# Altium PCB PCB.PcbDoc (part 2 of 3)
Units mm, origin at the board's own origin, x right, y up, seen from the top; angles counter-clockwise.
Board outline 120 x 100 mm, 4 copper layers (Top Layer, Mid-Layer 1, Mid-Layer 2, Bottom Layer); 85 components, 69 nets, 423 pads, 4470 vias.
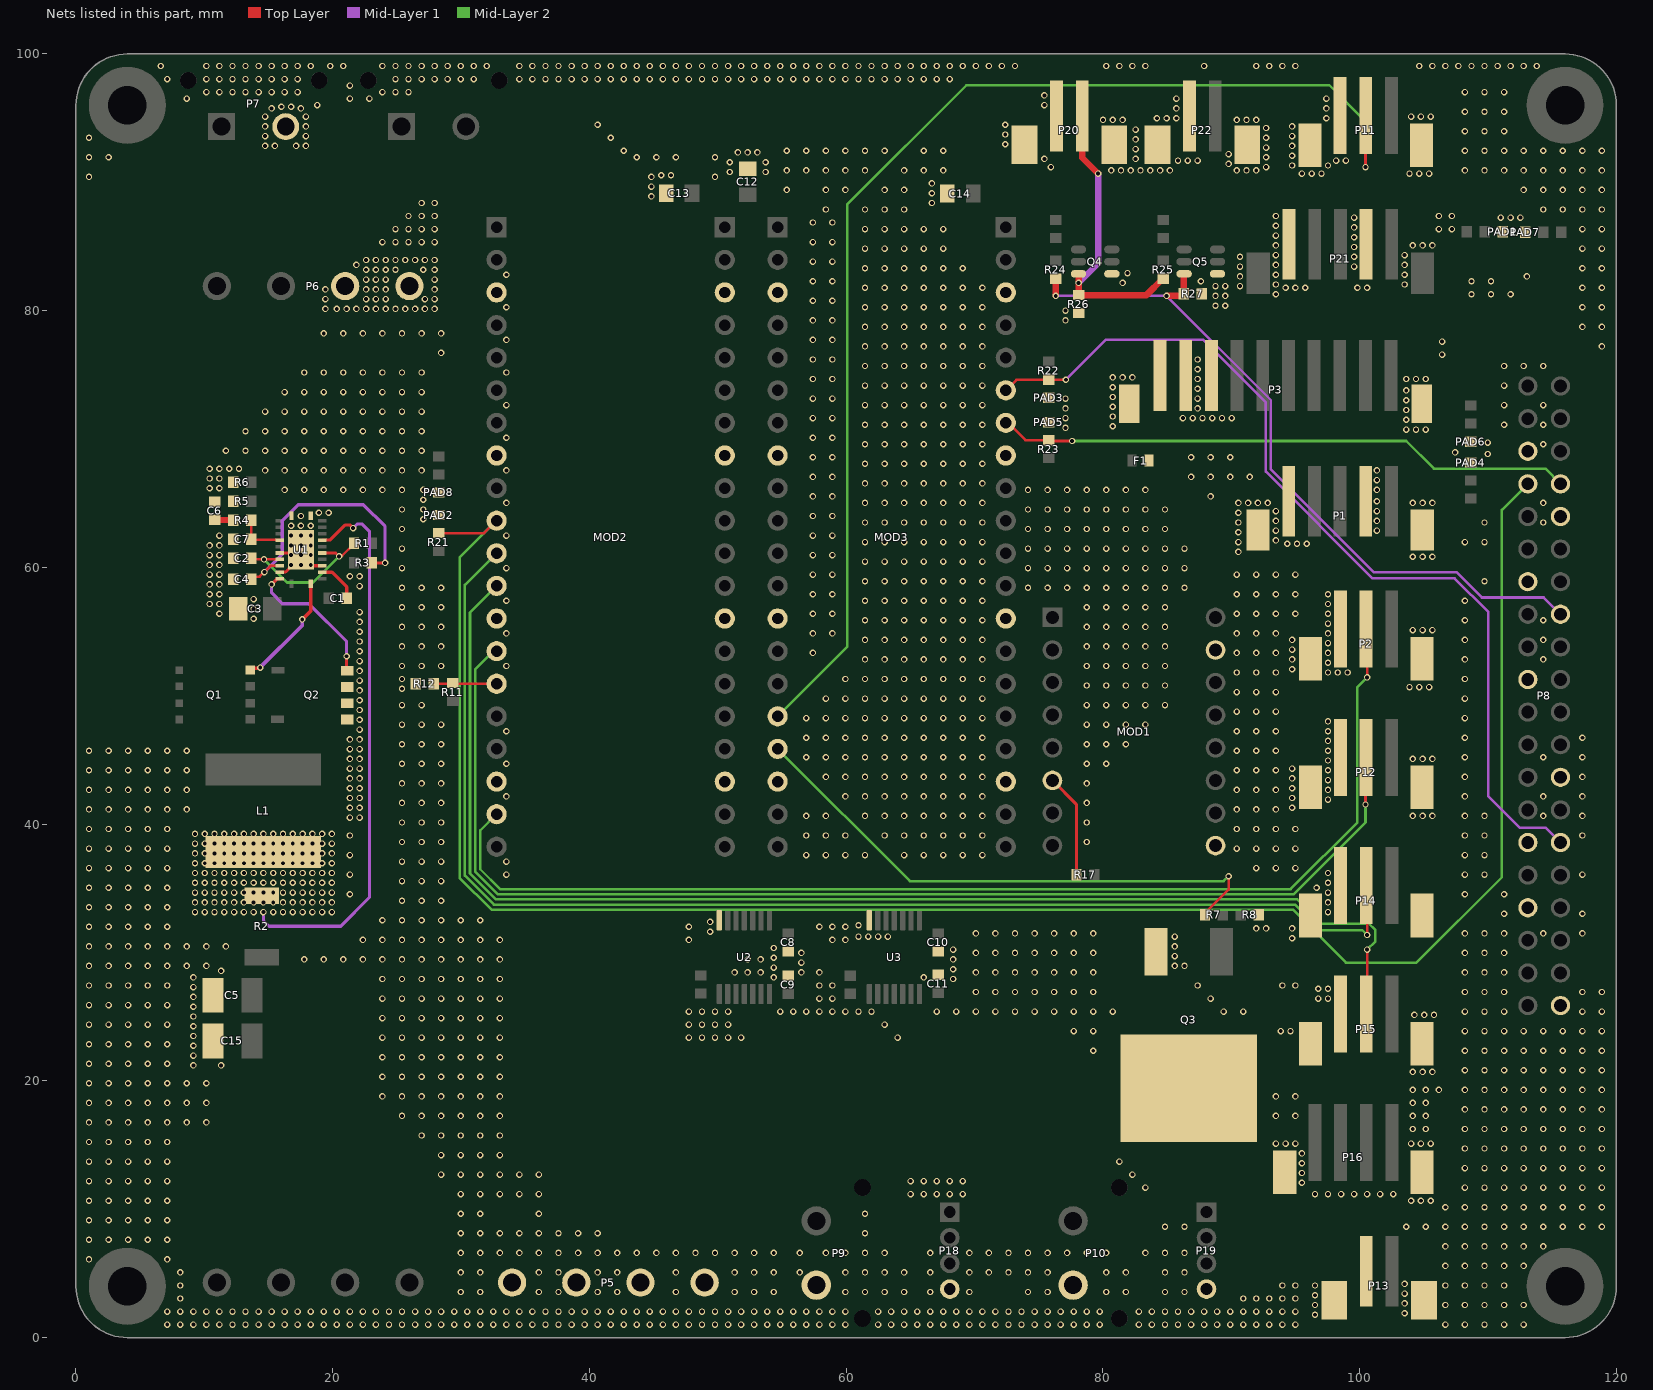
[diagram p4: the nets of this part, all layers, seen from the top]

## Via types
v1: diameter 0.5, hole 0.3, Top Layer to Bottom Layer, 4470 vias

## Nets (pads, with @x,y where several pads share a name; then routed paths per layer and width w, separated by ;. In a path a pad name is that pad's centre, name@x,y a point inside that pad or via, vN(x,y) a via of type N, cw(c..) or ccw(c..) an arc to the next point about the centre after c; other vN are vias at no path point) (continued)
ESP32-1_GPIO_18: MOD2.10 P8.8 R21.1 | length 152.1
  Top Layer w0.2: R21.1@28.245,62.676 31.802,62.676 MOD2.10@32.766,63.64
  Mid-Layer 2 w0.2: MOD2.10@32.766,63.64 29.896,60.77 29.896,35.824 32.385,33.335 94.808,33.335 98.933,29.21 104.419,29.21 111.074,35.865 111.074,64.478 P8.8@113.106,66.51
ESP32-1_GPIO_33: MOD2.11 P14.2 | length 102.2
  Top Layer w0.2: P14.2@100.514,35.206 100.584,35.136 v1(100.584,31.369)
  Mid-Layer 2 w0.2: MOD2.11@32.766,61.1 30.296,58.63 30.296,35.99 32.551,33.735 94.974,33.735 96.959,31.75 100.203,31.75 v1(100.584,31.369)
ESP32-1_GPIO_34: MOD2.12 P15.2 | length 102.4
  Top Layer w0.2: P15.2@100.514,25.206 100.584,25.275 v1(100.584,30.226)
  Mid-Layer 2 w0.2: MOD2.12@32.766,58.56 30.696,56.49 30.696,36.156 32.717,34.135 95.139,34.135 97.016,32.258 100.711,32.258 101.219,31.75 101.219,30.861 v1(100.584,30.226)
ESP32-1_GPIO_35: MOD2.14 P12.2 | length 95.5
  Top Layer w0.2: v1(100.457,41.529) 100.457,45.155 P12.2@100.508,45.206
  Mid-Layer 2 w0.2: MOD2.14@32.766,53.48 32.525,53.48 31.096,52.051 31.096,36.321 32.882,34.535 94.86,34.535 100.457,40.132 v1(100.457,41.529)
ESP32-1_GPIO_36: MOD2.15 R11.1 R12.2 | length 4.9
  Top Layer w0.2: R12.2@27.878,51.054 27.992,50.94 MOD2.15@32.766,50.94
ESP32-1_GPIO_39: MOD2.19 P2.2 | length 91.4
  Top Layer w0.2: P2.2@100.508,55.206 100.584,55.13 v1(100.584,51.435)
  Mid-Layer 2 w0.2: MOD2.19@32.766,40.78 31.496,39.51 31.496,36.487 33.048,34.935 94.625,34.935 99.822,40.132 99.822,50.673 v1(100.584,51.435)
ESP32-2_GPIO_9: MOD3.34 P8.7 R23.1 | length 45.2
  Top Layer w0.2: MOD3.34@72.44,71.26 72.631,71.26 73.973,69.918 R23.1@75.795,69.918 75.854,69.977 75.981,69.85 v1(77.597,69.85)
  Mid-Layer 2 w0.2: v1(77.597,69.85) 103.632,69.85 105.791,67.691 114.465,67.691 P8.7@115.646,66.51
ESP32-2_GPIO_10: MOD3.35 P8.29 R22.1 | length 72.6
  Top Layer w0.2: MOD3.35@72.44,73.8 73.254,74.614 R22.1@75.796,74.614 75.807,74.625 v1(77.114,74.625)
  Mid-Layer 1 w0.2: v1(77.114,74.625) 80.239,77.749 87.801,77.749 92.691,72.859 92.691,67.456 100.995,59.152 107.396,59.152 110.033,56.515 110.033,42.164 112.471,39.726 114.491,39.726 P8.29@115.646,38.57
ESP32-2_GPIO_37: MOD3.16 P11.2 | length 95.1
  Top Layer w0.2: v1(100.457,91.186) 100.457,95.187 P11.2@100.476,95.206
  Mid-Layer 2 w0.2: MOD3.16@54.66,48.4 60.071,53.811 60.071,88.265 69.367,97.561 97.638,97.561 100.457,94.742 v1(100.457,91.186)
ESP32-2_GPIO_38: MOD3.17 R7.2 | length 43.4
  Top Layer w0.2: R7.2@87.946,32.944 87.884,33.006 89.789,34.911 v1(89.789,35.941)
  Mid-Layer 2 w0.2: MOD3.17@54.66,45.86 64.96,35.56 89.408,35.56 v1(89.789,35.941)
FLP/FLP_INPUT1: P20.1 Q4.3 R25.2 R26.2 | length 22.9
  Top Layer w0.5: Q4.3@78.1,82.87 78.103,82.868 78.103,81.22 R26.2@78.105,81.218 83.392,81.218 84.659,82.485 R25.2@84.709,82.485 ; P20.1@78.389,95.168 78.389,91.918 v1(79.629,90.678)
  Mid-Layer 1 w0.5: v1(78.105,82.169) 79.629,83.693 v1(79.629,90.678)
FLP/FLP_INPUT2_RSPI22: P8.15 Q5.3 R24.1 R27.2 | length 57.2
  Top Layer w0.5: v1(76.327,81.153) 76.327,82.231 76.454,82.358 R24.1@76.327,82.485 ; v1(84.963,81.153) 86.143,81.153 R27.2@86.295,81.306 86.313,81.323 86.313,82.853 Q5.3@86.33,82.87
  Mid-Layer 1 w0.2: v1(76.327,81.153) v1(84.963,81.153) 93.091,73.025 93.091,67.64 101.092,59.639 107.544,59.639 109.525,57.658 114.338,57.658 P8.15@115.646,56.35
GND: C2.2 C3.1 C4.1 C5.1 C6.2 C7.2 C8.1 C9.1 C10.1 C11.1 C12.1 C13.1 C14.1 C15.1 MOD1.9 MOD1.15 MOD2.3 MOD2.8 MOD2.13 MOD2.18 MOD2.23 MOD2.28 MOD2.33 MOD2.38 MOD3.3 MOD3.8 MOD3.13 MOD3.18 MOD3.23 MOD3.28 MOD3.33 MOD3.38 P1.2 P1.5 P1.MP P2.3 P2.MP P3.8 P3.9 P3.MP P5.1 P5.2 P5.3 P5.4 P6.3 P6.4 P7.2 P8.6 P8.9 P8.14 P8.20 P8.25 P8.30 P8.34 P8.39 P9.2 P10.2 P11.3 P11.MP P12.3 P12.MP P13.MP P14.3 P14.MP P15.3 P15.MP P16.MP P18.4 P19.4 P20.2 P20.MP P21.2 P21.5 P22.2 P22.MP PAD1.1 PAD2.1 PAD3.1 PAD4.1 PAD5.1 PAD6.1 PAD7.1 PAD8.1 Q2.1 Q2.2 Q2.3 Q3.3 Q4.4 Q5.4 R5.2 R6.2 R8.1 R12.1 R26.1 R27.1 U1.1 U1.7 U1.10 U1.16 U1.24 U1.25 U2.7 U3.7 | length 3.1
  Top Layer w0.25: U1.10@15.88,59.626 15.895,59.641 16.328,59.641 16.764,60.077 v1(16.764,60.198) ; U1.7@15.88,61.126 16.598,61.126 v1(16.764,60.96) ; v1(18.288,60.198) 18.36,60.126 U1.16@19.195,60.126
  other v1: 7.112,1.016 8.128,1.016 9.144,1.016 10.16,1.016 11.176,1.016 12.192,1.016 13.208,1.016 14.224,1.016 15.24,1.016 16.256,1.016 17.272,1.016 18.288,1.016 19.304,1.016 20.32,1.016 21.336,1.016 22.352,1.016 23.368,1.016 24.384,1.016 25.4,1.016 26.416,1.016 27.432,1.016 28.448,1.016 29.464,1.016 30.48,1.016 31.496,1.016 32.512,1.016 33.528,1.016 34.544,1.016 35.56,1.016 36.576,1.016 37.592,1.016 38.608,1.016 39.624,1.016 40.64,1.016 41.656,1.016 42.672,1.016 43.688,1.016 44.704,1.016 45.72,1.016 46.736,1.016 47.752,1.016 48.768,1.016 49.784,1.016 50.8,1.016 51.816,1.016 52.832,1.016 53.848,1.016 54.864,1.016 55.88,1.016 56.896,1.016 57.912,1.016 58.928,1.016 59.944,1.016 62.484,1.016 63.5,1.016 64.516,1.016 65.532,1.016 66.548,1.016 67.564,1.016 68.58,1.016 69.596,1.016 70.612,1.016 71.628,1.016 72.644,1.016 73.66,1.016 74.676,1.016 75.692,1.016 76.708,1.016 77.724,1.016 78.74,1.016 79.756,1.016 82.804,1.016 83.82,1.016 84.836,1.016 85.852,1.016 86.868,1.016 87.884,1.016 88.9,1.016 89.916,1.016 90.932,1.016 91.948,1.016 92.964,1.016 93.98,1.016 94.996,1.016 106.68,1.016 108.204,1.016 109.728,1.016 111.252,1.016 112.776,1.016 96.52,1.778 103.505,1.905 7.112,2.032 8.128,2.032 9.144,2.032 10.16,2.032 11.176,2.032 12.192,2.032 13.208,2.032 14.224,2.032 15.24,2.032 16.256,2.032 17.272,2.032 18.288,2.032 19.304,2.032 20.32,2.032 21.336,2.032 22.352,2.032 23.368,2.032 24.384,2.032 25.4,2.032 26.416,2.032 27.432,2.032 28.448,2.032 29.464,2.032 30.48,2.032 31.496,2.032 32.512,2.032 33.528,2.032 34.544,2.032 35.56,2.032 36.576,2.032 37.592,2.032 38.608,2.032 39.624,2.032 40.64,2.032 41.656,2.032 42.672,2.032 43.688,2.032 44.704,2.032 45.72,2.032 46.736,2.032 47.752,2.032 48.768,2.032 49.784,2.032 50.8,2.032 51.816,2.032 52.832,2.032 53.848,2.032 54.864,2.032 55.88,2.032 56.896,2.032 57.912,2.032 58.928,2.032 59.944,2.032 62.484,2.032 63.5,2.032 64.516,2.032 65.532,2.032 66.548,2.032 67.564,2.032 68.58,2.032 69.596,2.032 70.612,2.032 71.628,2.032 72.644,2.032 73.66,2.032 74.676,2.032 75.692,2.032 76.708,2.032 77.724,2.032 78.74,2.032 79.756,2.032 82.804,2.032 83.82,2.032 84.836,2.032 85.852,2.032 86.868,2.032 87.884,2.032 88.9,2.032 89.916,2.032 90.932,2.032 91.948,2.032 92.964,2.032 93.98,2.032 94.996,2.032 96.52,2.54 106.68,2.54 108.204,2.54 109.728,2.54 111.252,2.54 112.776,2.54 103.505,2.667 8.128,3.048 90.932,3.048 91.948,3.048 92.964,3.048 93.98,3.048 94.996,3.048 96.52,3.302 103.505,3.429 29.972,3.556 31.496,3.556 36.068,3.556 37.592,3.556 40.64,3.556 42.164,3.556 46.736,3.556 51.308,3.556 52.832,3.556 54.356,3.556 59.944,3.556 61.468,3.556 62.992,3.556 64.516,3.556 66.548,3.556 69.596,3.556 74.168,3.556 75.692,3.556 80.264,3.556 81.788,3.556 84.836,3.556 86.36,3.556 8.128,4.064 93.98,4.064 94.996,4.064 96.52,4.064 106.68,4.064 108.204,4.064 109.728,4.064 111.252,4.064 103.505,4.191 8.128,5.08 29.972,5.08 31.496,5.08 36.068,5.08 37.592,5.08 40.64,5.08 42.164,5.08 46.736,5.08 51.308,5.08 52.832,5.08 54.356,5.08 56.388,5.08 59.944,5.08 61.468,5.08 62.992,5.08 64.516,5.08 66.548,5.08 69.596,5.08 71.12,5.08 72.644,5.08 74.168,5.08 75.692,5.08 80.264,5.08 81.788,5.08 84.836,5.08 86.36,5.08 106.68,5.588 108.204,5.588 109.728,5.588 111.252,5.588 112.776,5.588 1.016,6.096 7.112,6.096 29.972,6.604 31.496,6.604 33.02,6.604 34.544,6.604 36.068,6.604 37.592,6.604 39.116,6.604 40.64,6.604 42.164,6.604 43.688,6.604 45.212,6.604 46.736,6.604 48.26,6.604 49.784,6.604 51.308,6.604 52.832,6.604 54.356,6.604 56.388,6.604 58.42,6.604 59.944,6.604 61.468,6.604 62.992,6.604 66.548,6.604 69.596,6.604 71.12,6.604 72.644,6.604 74.168,6.604 75.692,6.604 77.216,6.604 78.74,6.604 80.264,6.604 83.312,6.604 84.836,6.604 86.36,6.604 106.68,7.112 108.204,7.112 109.728,7.112 111.252,7.112 112.776,7.112 114.3,7.112 1.016,7.62 2.54,7.62 4.064,7.62 5.588,7.62 7.112,7.62 29.972,8.128 31.496,8.128 33.02,8.128 34.544,8.128 36.068,8.128 37.592,8.128 39.116,8.128 40.64,8.128 61.468,8.128 84.836,8.636 86.36,8.636 103.632,8.636 105.156,8.636 106.68,8.636 108.204,8.636 109.728,8.636 111.252,8.636 112.776,8.636 114.3,8.636 115.824,8.636 117.348,8.636 118.872,8.636 1.016,9.144 2.54,9.144 4.064,9.144 5.588,9.144 7.112,9.144 29.972,9.652 31.496,9.652 36.068,9.652 61.468,9.652 106.68,10.16 108.204,10.16 109.728,10.16 111.252,10.16 112.776,10.16 114.3,10.16 115.824,10.16 117.348,10.16 118.872,10.16 1.016,10.668 2.54,10.668 4.064,10.668 5.588,10.668 7.112,10.668 104.013,10.668 104.775,10.668 105.537,10.668 29.972,11.176 31.496,11.176 33.02,11.176 34.544,11.176 36.068,11.176 65.024,11.176 66.04,11.176 67.056,11.176 68.072,11.176 69.088,11.176 96.52,11.176 97.536,11.176 98.552,11.176 99.568,11.176 100.584,11.176 101.6,11.176 102.616,11.176 83.312,11.684 108.204,11.684 109.728,11.684 111.252,11.684 112.776,11.684 114.3,11.684 115.824,11.684 117.348,11.684 118.872,11.684 95.504,12.065 1.016,12.192 2.54,12.192 4.064,12.192 5.588,12.192 7.112,12.192 65.024,12.192 66.04,12.192 67.056,12.192 68.072,12.192 69.088,12.192 28.448,12.7 29.972,12.7 31.496,12.7 33.02,12.7 34.544,12.7 36.068,12.7 82.296,12.7 95.504,12.827 108.204,13.208 109.728,13.208 111.252,13.208 112.776,13.208 114.3,13.208 115.824,13.208 117.348,13.208 118.872,13.208 95.504,13.589 1.016,13.716 2.54,13.716 4.064,13.716 5.588,13.716 7.112,13.716 81.28,13.716 28.448,14.224 29.972,14.224 31.496,14.224 33.02,14.224 95.504,14.351 108.204,14.732 109.728,14.732 111.252,14.732 112.776,14.732 114.3,14.732 115.824,14.732 117.348,14.732 118.872,14.732 93.472,15.113 94.234,15.113 94.996,15.113 104.013,15.113 104.775,15.113 105.537,15.113 1.016,15.24 2.54,15.24 4.064,15.24 5.588,15.24 7.112,15.24 26.924,15.748 28.448,15.748 29.972,15.748 31.496,15.748 33.02,15.748 104.14,16.256 105.156,16.256 108.204,16.256 109.728,16.256 111.252,16.256 112.776,16.256 114.3,16.256 115.824,16.256 117.348,16.256 118.872,16.256 1.016,16.764 2.54,16.764 4.064,16.764 5.588,16.764 7.112,16.764 8.636,16.764 10.16,16.764 25.4,17.272 26.924,17.272 28.448,17.272 29.972,17.272 31.496,17.272 33.02,17.272 93.472,17.272 94.996,17.272 104.14,17.272 105.156,17.272 108.204,17.78 109.728,17.78 111.252,17.78 112.776,17.78 114.3,17.78 115.824,17.78 117.348,17.78 118.872,17.78 1.016,18.288 2.54,18.288 4.064,18.288 5.588,18.288 7.112,18.288 8.636,18.288 10.16,18.288 104.14,18.288 105.156,18.288 23.876,18.796 25.4,18.796 26.924,18.796 28.448,18.796 29.972,18.796 31.496,18.796 33.02,18.796 93.472,18.796 94.996,18.796 104.14,19.304 105.156,19.304 106.172,19.304 108.204,19.304 109.728,19.304 111.252,19.304 112.776,19.304 114.3,19.304 115.824,19.304 117.348,19.304 118.872,19.304 1.016,19.812 2.54,19.812 4.064,19.812 5.588,19.812 7.112,19.812 8.636,19.812 10.16,19.812 23.876,20.32 25.4,20.32 26.924,20.32 28.448,20.32 29.972,20.32 31.496,20.32 33.02,20.32 104.14,20.701 104.902,20.701 105.664,20.701 108.204,20.828 109.728,20.828 111.252,20.828 112.776,20.828 114.3,20.828 115.824,20.828 117.348,20.828 118.872,20.828 9.144,21.209 11.303,21.209 1.016,21.336 2.54,21.336 4.064,21.336 5.588,21.336 7.112,21.336 23.876,21.844 25.4,21.844 26.924,21.844 28.448,21.844 29.972,21.844 31.496,21.844 33.02,21.844 9.144,21.971 79.248,22.352 108.204,22.352 109.728,22.352 111.252,22.352 112.776,22.352 114.3,22.352 115.824,22.352 117.348,22.352 118.872,22.352 9.144,22.733 1.016,22.86 2.54,22.86 4.064,22.86 5.588,22.86 7.112,22.86 23.876,23.368 25.4,23.368 26.924,23.368 28.448,23.368 29.972,23.368 31.496,23.368 33.02,23.368 47.752,23.368 48.768,23.368 49.784,23.368 50.8,23.368 51.816,23.368 64.008,23.368 9.144,23.495 77.724,23.876 79.248,23.876 93.853,23.876 94.615,23.876 108.204,23.876 109.728,23.876 111.252,23.876 112.776,23.876 114.3,23.876 115.824,23.876 117.348,23.876 118.872,23.876 9.144,24.257 1.016,24.384 2.54,24.384 4.064,24.384 5.588,24.384 7.112,24.384 47.752,24.384 48.768,24.384 49.784,24.384 50.8,24.384 62.992,24.384 23.876,24.892 25.4,24.892 26.924,24.892 28.448,24.892 29.972,24.892 31.496,24.892 33.02,24.892 9.144,25.019 104.267,25.146 105.029,25.146 105.791,25.146 47.752,25.4 48.768,25.4 49.784,25.4 50.8,25.4 54.864,25.4 55.88,25.4 56.896,25.4 57.912,25.4 58.928,25.4 59.944,25.4 60.96,25.4 61.976,25.4 67.056,25.4 68.58,25.4 70.104,25.4 71.628,25.4 73.152,25.4 74.676,25.4 76.2,25.4 77.724,25.4 79.248,25.4 80.772,25.4 89.408,25.4 90.932,25.4 108.204,25.4 109.728,25.4 111.252,25.4 117.348,25.4 118.872,25.4 9.144,25.781 1.016,25.908 2.54,25.908 4.064,25.908 5.588,25.908 7.112,25.908 23.876,26.416 25.4,26.416 26.924,26.416 28.448,26.416 29.972,26.416 31.496,26.416 33.02,26.416 57.912,26.416 58.928,26.416 88.392,26.416 96.774,26.416 97.536,26.416 9.144,26.543 70.104,26.924 71.628,26.924 73.152,26.924 74.676,26.924 76.2,26.924 77.724,26.924 79.248,26.924 108.204,26.924 109.728,26.924 111.252,26.924 117.348,26.924 118.872,26.924 96.774,27.178 97.536,27.178 9.144,27.305 1.016,27.432 2.54,27.432 4.064,27.432 5.588,27.432 7.112,27.432 57.912,27.432 58.928,27.432 87.376,27.432 93.98,27.432 94.996,27.432 23.876,27.94 25.4,27.94 26.924,27.94 28.448,27.94 29.972,27.94 31.496,27.94 33.02,27.94 68.326,27.94 9.144,28.067 54.356,28.067 66.04,28.067 51.308,28.448 52.324,28.448 53.34,28.448 56.515,28.448 57.912,28.448 70.104,28.448 71.628,28.448 73.152,28.448 74.676,28.448 76.2,28.448 77.724,28.448 79.248,28.448 108.204,28.448 109.728,28.448 111.252,28.448 11.303,28.575 68.326,28.702 54.356,28.829 1.016,28.956 2.54,28.956 4.064,28.956 5.588,28.956 7.112,28.956 8.636,28.956 10.16,28.956 85.598,28.956 86.36,28.956 56.515,29.21 17.78,29.464 19.304,29.464 20.828,29.464 22.352,29.464 23.876,29.464 25.4,29.464 26.924,29.464 28.448,29.464 29.972,29.464 31.496,29.464 33.02,29.464 52.324,29.464 53.34,29.464 68.326,29.464 54.356,29.591 85.598,29.718 56.515,29.972 70.104,29.972 71.628,29.972 73.152,29.972 74.676,29.972 76.2,29.972 77.724,29.972 79.248,29.972 108.204,29.972 109.728,29.972 111.252,29.972 68.326,30.226 54.356,30.353 1.016,30.48 2.54,30.48 4.064,30.48 5.588,30.48 7.112,30.48 8.636,30.48 10.16,30.48 11.684,30.48 85.598,30.48 22.352,30.988 23.876,30.988 25.4,30.988 26.924,30.988 28.448,30.988 29.972,30.988 31.496,30.988 33.02,30.988 47.752,30.988 58.928,30.988 59.944,30.988 94.742,31.115 60.96,31.242 61.722,31.242 62.484,31.242 63.246,31.242 85.598,31.242 70.104,31.496 71.628,31.496 73.152,31.496 74.676,31.496 76.2,31.496 77.724,31.496 79.248,31.496 108.204,31.496 109.728,31.496 111.252,31.496 114.3,31.496 117.348,31.496 49.403,31.623 91.948,31.877 92.71,31.877 94.742,31.877 1.016,32.004 2.54,32.004 4.064,32.004 5.588,32.004 7.112,32.004 47.752,32.004 57.912,32.004 58.928,32.004 59.944,32.004 60.96,32.131 49.403,32.385 23.876,32.512 25.4,32.512 26.924,32.512 28.448,32.512 29.972,32.512 31.496,32.512 111.252,33.02 117.348,33.02 97.536,33.147 1.016,33.528 2.54,33.528 4.064,33.528 5.588,33.528 7.112,33.528 97.536,33.909 25.4,34.036 26.924,34.036 28.448,34.036 21.336,34.544 108.204,34.544 111.252,34.544 97.536,34.671 1.016,35.052 2.54,35.052 4.064,35.052 5.588,35.052 7.112,35.052 96.647,35.052 97.536,35.433 25.4,35.56 26.924,35.56 28.448,35.56 21.336,36.068 33.528,36.068 108.204,36.068 109.728,36.068 117.348,36.068 97.536,36.195 1.016,36.576 2.54,36.576 4.064,36.576 5.588,36.576 7.112,36.576 91.948,36.576 93.472,36.576 94.996,36.576 25.4,37.084 26.924,37.084 28.448,37.084 33.528,37.084 21.336,37.592 56.896,37.592 58.42,37.592 59.944,37.592 61.468,37.592 64.516,37.592 66.04,37.592 67.564,37.592 69.088,37.592 70.612,37.592 108.204,37.592 109.728,37.592 1.016,38.1 2.54,38.1 4.064,38.1 5.588,38.1 7.112,38.1 90.424,38.1 91.948,38.1 93.472,38.1 94.996,38.1 25.4,38.608 26.924,38.608 28.448,38.608 78.74,38.608 21.336,39.116 56.896,39.116 58.42,39.116 59.944,39.116 62.992,39.116 64.516,39.116 66.04,39.116 67.564,39.116 69.088,39.116 70.612,39.116 108.204,39.116 109.728,39.116 117.348,39.116 1.016,39.624 2.54,39.624 4.064,39.624 5.588,39.624 7.112,39.624 90.424,39.624 91.948,39.624 93.472,39.624 94.996,39.624 25.4,40.132 26.924,40.132 28.448,40.132 78.74,40.132 21.336,40.513 22.098,40.513 56.896,40.64 58.42,40.64 61.468,40.64 62.992,40.64 64.516,40.64 66.04,40.64 67.564,40.64 69.088,40.64 70.612,40.64 104.14,40.64 104.902,40.64 105.664,40.64 108.204,40.64 109.728,40.64 114.3,40.64 117.348,40.64 1.016,41.148 2.54,41.148 4.064,41.148 5.588,41.148 7.112,41.148 8.636,41.148 90.424,41.148 91.948,41.148 93.472,41.148 21.336,41.275 22.098,41.275 94.742,41.275 25.4,41.656 26.924,41.656 28.448,41.656 78.74,41.656 97.536,41.91 21.336,42.037 22.098,42.037 94.742,42.037 33.528,42.164 59.944,42.164 61.468,42.164 62.992,42.164 64.516,42.164 66.04,42.164 67.564,42.164 69.088,42.164 70.612,42.164 108.204,42.164 114.3,42.164 117.348,42.164 1.016,42.672 2.54,42.672 4.064,42.672 5.588,42.672 7.112,42.672 8.636,42.672 90.424,42.672 91.948,42.672 93.472,42.672 97.536,42.672 21.336,42.799 22.098,42.799 94.742,42.799 25.4,43.18 26.924,43.18 28.448,43.18 78.74,43.18 97.536,43.434 21.336,43.561 22.098,43.561 94.742,43.561 58.42,43.688 59.944,43.688 61.468,43.688 62.992,43.688 64.516,43.688 66.04,43.688 67.564,43.688 69.088,43.688 70.612,43.688 108.204,43.688 117.348,43.688 1.016,44.196 2.54,44.196 4.064,44.196 5.588,44.196 7.112,44.196 8.636,44.196 90.424,44.196 91.948,44.196 93.472,44.196 97.536,44.196 21.336,44.323 22.098,44.323 94.742,44.323 25.4,44.704 26.924,44.704 28.448,44.704 33.528,44.704 78.74,44.704 80.264,44.704 97.536,44.958 21.336,45.085 22.098,45.085 104.14,45.085 104.902,45.085 105.664,45.085 56.896,45.212 58.42,45.212 59.944,45.212 61.468,45.212 62.992,45.212 64.516,45.212 66.04,45.212 67.564,45.212 69.088,45.212 70.612,45.212 108.204,45.212 114.3,45.212 117.348,45.212 1.016,45.72 2.54,45.72 4.064,45.72 5.588,45.72 7.112,45.72 8.636,45.72 90.424,45.72 91.948,45.72 93.472,45.72 97.536,45.72 21.336,45.847 22.098,45.847 25.4,46.228 26.924,46.228 28.448,46.228 78.74,46.228 80.264,46.228 81.788,46.228 97.536,46.482 21.336,46.609 22.098,46.609 56.896,46.736 58.42,46.736 59.944,46.736 61.468,46.736 62.992,46.736 64.516,46.736 66.04,46.736 67.564,46.736 69.088,46.736 70.612,46.736 108.204,46.736 117.348,46.736 33.528,47.244 90.424,47.244 91.948,47.244 93.472,47.244 97.536,47.244 22.098,47.371 25.4,47.752 26.924,47.752 28.448,47.752 78.74,47.752 80.264,47.752 81.788,47.752 83.312,47.752 97.536,48.006 22.098,48.133 56.896,48.26 58.42,48.26 59.944,48.26 61.468,48.26 62.992,48.26 64.516,48.26 66.04,48.26 67.564,48.26 69.088,48.26 70.612,48.26 108.204,48.26 90.424,48.768 91.948,48.768 93.472,48.768 22.098,48.895 25.4,49.276 26.924,49.276 78.74,49.276 80.264,49.276 81.788,49.276 83.312,49.276 84.836,49.276 22.098,49.657 58.42,49.784 59.944,49.784 61.468,49.784 62.992,49.784 64.516,49.784 66.04,49.784 67.564,49.784 69.088,49.784 70.612,49.784 108.204,49.784 90.424,50.292 91.948,50.292 93.472,50.292 22.098,50.419 25.4,50.546 103.886,50.673 104.648,50.673 105.41,50.673 78.74,50.8 80.264,50.8 81.788,50.8 83.312,50.8 84.836,50.8 22.098,51.181 25.4,51.308 59.944,51.308 61.468,51.308 62.992,51.308 64.516,51.308 66.04,51.308 67.564,51.308 69.088,51.308 70.612,51.308 108.204,51.308 90.424,51.816 91.948,51.816 93.472,51.816 97.536,51.816 98.298,51.816 99.06,51.816 22.098,51.943 94.742,52.07 25.4,52.324 26.924,52.324 28.448,52.324 33.528,52.324 78.74,52.324 80.264,52.324 81.788,52.324 83.312,52.324 84.836,52.324 97.536,52.578 22.098,52.705 61.468,52.832 62.992,52.832 64.516,52.832 66.04,52.832 67.564,52.832 69.088,52.832 70.612,52.832 94.742,52.832 108.204,52.832 114.3,52.832 57.404,53.34 90.424,53.34 91.948,53.34 93.472,53.34 97.536,53.34 22.098,53.467 94.742,53.594 25.4,53.848 26.924,53.848 28.448,53.848 78.74,53.848 80.264,53.848 81.788,53.848 83.312,53.848 84.836,53.848 97.536,54.102 22.098,54.229 61.468,54.356 62.992,54.356 64.516,54.356 66.04,54.356 67.564,54.356 69.088,54.356 70.612,54.356 94.742,54.356 108.204,54.356 114.3,54.356 33.528,54.864 57.404,54.864 58.928,54.864 90.424,54.864 91.948,54.864 93.472,54.864 97.536,54.864 22.098,54.991 104.14,55.118 104.902,55.118 105.664,55.118 25.4,55.372 26.924,55.372 28.448,55.372 78.74,55.372 80.264,55.372 81.788,55.372 83.312,55.372 84.836,55.372 97.536,55.626 22.098,55.753 61.468,55.88 62.992,55.88 64.516,55.88 66.04,55.88 67.564,55.88 69.088,55.88 70.612,55.88 108.204,55.88 114.3,55.88 13.843,56.007 11.176,56.388 57.404,56.388 58.928,56.388 90.424,56.388 91.948,56.388 93.472,56.388 94.996,56.388 97.536,56.388 22.098,56.515 13.843,56.769 25.4,56.896 26.924,56.896 28.448,56.896 78.74,56.896 80.264,56.896 81.788,56.896 83.312,56.896 84.836,56.896 10.414,57.15 11.176,57.15 97.536,57.15 33.528,57.404 61.468,57.404 62.992,57.404 64.516,57.404 66.04,57.404 67.564,57.404 69.088,57.404 70.612,57.404 108.204,57.404 13.843,57.531 10.414,57.912 11.176,57.912 57.404,57.912 58.928,57.912 90.424,57.912 91.948,57.912 93.472,57.912 94.996,57.912 97.536,57.912 25.4,58.42 26.924,58.42 28.448,58.42 74.168,58.42 75.692,58.42 77.216,58.42 78.74,58.42 80.264,58.42 81.788,58.42 83.312,58.42 84.836,58.42 86.36,58.42 22.098,58.547 10.414,58.674 11.176,58.674 61.468,58.928 62.992,58.928 64.516,58.928 66.04,58.928 67.564,58.928 69.088,58.928 70.612,58.928 109.728,58.928 21.336,59.309 22.098,59.309 10.414,59.436 11.176,59.436 57.404,59.436 58.928,59.436 90.424,59.436 91.948,59.436 93.472,59.436 94.996,59.436 25.4,59.944 33.528,59.944 74.168,59.944 75.692,59.944 77.216,59.944 78.74,59.944 80.264,59.944 81.788,59.944 83.312,59.944 84.836,59.944 86.36,59.944 10.414,60.198 11.176,60.198 17.526,60.198 61.468,60.452 62.992,60.452 64.516,60.452 66.04,60.452 67.564,60.452 69.088,60.452 70.612,60.452 104.14,60.833 104.902,60.833 105.664,60.833 10.414,60.96 11.176,60.96 17.526,60.96 18.288,60.96 57.404,60.96 58.928,60.96 90.551,61.214 25.4,61.468 74.168,61.468 75.692,61.468 77.216,61.468 78.74,61.468 80.264,61.468 81.788,61.468 83.312,61.468 84.836,61.468 86.36,61.468 10.414,61.722 11.176,61.722 16.764,61.722 17.526,61.722 18.288,61.722 94.361,61.849 95.123,61.849 95.885,61.849 61.468,61.976 62.992,61.976 64.516,61.976 66.04,61.976 67.564,61.976 69.088,61.976 70.612,61.976 90.551,61.976 108.204,61.976 109.728,61.976 93.472,62.103 11.176,62.484 16.764,62.484 17.526,62.484 18.288,62.484 33.528,62.484 57.404,62.484 58.928,62.484 90.551,62.738 93.472,62.865 101.346,62.865 25.4,62.992 74.168,62.992 75.692,62.992 77.216,62.992 78.74,62.992 80.264,62.992 81.788,62.992 83.312,62.992 84.836,62.992 16.764,63.246 17.526,63.246 18.288,63.246 61.468,63.5 62.992,63.5 64.516,63.5 66.04,63.5 67.564,63.5 69.088,63.5 70.612,63.5 90.551,63.5 109.728,63.5 114.3,63.5 93.472,63.627 101.346,63.627 27.051,63.754 17.526,64.008 57.404,64.008 58.928,64.008 18.923,64.262 19.685,64.262 90.551,64.262 93.472,64.389 101.346,64.389 25.4,64.516 27.051,64.516 74.168,64.516 75.692,64.516 77.216,64.516 78.74,64.516 80.264,64.516 81.788,64.516 83.312,64.516 84.836,64.516 33.528,65.024 61.468,65.024 62.992,65.024 64.516,65.024 66.04,65.024 67.564,65.024 69.088,65.024 70.612,65.024 90.551,65.024 91.313,65.024 92.075,65.024 92.837,65.024 104.14,65.024 104.902,65.024 105.664,65.024 114.3,65.024 101.346,65.151 27.051,65.278 57.404,65.532 58.928,65.532 88.392,65.532 16.256,66.04 17.78,66.04 19.304,66.04 20.828,66.04 22.352,66.04 23.876,66.04 25.4,66.04 27.051,66.04 74.168,66.04 75.692,66.04 77.216,66.04 78.74,66.04 80.264,66.04 81.788,66.04 83.312,66.04 101.346,66.04 10.414,66.167 11.176,66.167 61.468,66.548 62.992,66.548 64.516,66.548 66.04,66.548 67.564,66.548 69.088,66.548 70.612,66.548 101.346,66.802 10.414,66.929 11.176,66.929 57.404,67.056 58.928,67.056 86.868,67.056 88.392,67.056 89.916,67.056 91.44,67.056 14.732,67.564 16.256,67.564 17.78,67.564 19.304,67.564 20.828,67.564 22.352,67.564 23.876,67.564 25.4,67.564 26.924,67.564 33.528,67.564 101.346,67.564 10.414,67.691 11.176,67.691 11.938,67.691 12.7,67.691 61.468,68.072 62.992,68.072 64.516,68.072 66.04,68.072 67.564,68.072 69.088,68.072 70.612,68.072 57.404,68.58 58.928,68.58 86.868,68.58 88.392,68.58 89.916,68.58 109.982,68.834 107.442,68.961 11.684,69.088 13.208,69.088 14.732,69.088 16.256,69.088 17.78,69.088 19.304,69.088 20.828,69.088 22.352,69.088 23.876,69.088 25.4,69.088 26.924,69.088 61.468,69.596 62.992,69.596 64.516,69.596 66.04,69.596 67.564,69.596 69.088,69.596 70.612,69.596 114.3,69.596 109.982,69.723 33.528,70.104 57.404,70.104 58.928,70.104 13.208,70.612 14.732,70.612 16.256,70.612 17.78,70.612 19.304,70.612 20.828,70.612 22.352,70.612 23.876,70.612 25.4,70.612 26.924,70.612 103.632,70.739 104.394,70.739 105.156,70.739 77.089,70.866 80.772,70.993 61.468,71.12 62.992,71.12 64.516,71.12 66.04,71.12 67.564,71.12 69.088,71.12 70.612,71.12 111.252,71.12 114.3,71.12 103.632,71.501 57.404,71.628 58.928,71.628 77.089,71.628 86.233,71.628 86.995,71.628 87.757,71.628 88.519,71.628 89.281,71.628 90.043,71.628 80.772,71.755 14.732,72.136 16.256,72.136 17.78,72.136 19.304,72.136 20.828,72.136 22.352,72.136 23.876,72.136 25.4,72.136 26.924,72.136 103.632,72.263 77.089,72.39 87.376,72.39 80.772,72.517 33.528,72.644 61.468,72.644 62.992,72.644 64.516,72.644 66.04,72.644 67.564,72.644 69.088,72.644 70.612,72.644 111.252,72.644 114.3,72.644 103.632,73.025 57.404,73.152 58.928,73.152 77.089,73.152 87.376,73.152 80.772,73.279 16.256,73.66 17.78,73.66 19.304,73.66 20.828,73.66 22.352,73.66 23.876,73.66 25.4,73.66 26.924,73.66 103.632,73.787 87.376,73.914 80.772,74.041 61.468,74.168 62.992,74.168 64.516,74.168 66.04,74.168 67.564,74.168 69.088,74.168 70.612,74.168 111.252,74.168 57.404,74.676 58.928,74.676 87.376,74.676 103.632,74.676 104.394,74.676 105.156,74.676 80.772,74.803 81.534,74.803 82.296,74.803 17.78,75.184 19.304,75.184 20.828,75.184 22.352,75.184 23.876,75.184 25.4,75.184 26.924,75.184 33.528,75.184 87.376,75.438 61.468,75.692 62.992,75.692 64.516,75.692 66.04,75.692 67.564,75.692 69.088,75.692 70.612,75.692 111.252,75.692 112.776,75.692 114.3,75.692 57.404,76.2 58.928,76.2 87.376,76.2 106.426,76.581 28.448,76.708 61.468,77.216 62.992,77.216 64.516,77.216 66.04,77.216 67.564,77.216 69.088,77.216 70.612,77.216 118.872,77.216 106.426,77.597 33.528,77.724 57.404,77.724 58.928,77.724 19.304,78.232 20.828,78.232 22.352,78.232 23.876,78.232 25.4,78.232 26.924,78.232 28.448,78.232 61.468,78.74 62.992,78.74 64.516,78.74 66.04,78.74 67.564,78.74 69.088,78.74 70.612,78.74 117.348,78.74 118.872,78.74 57.404,79.248 58.928,79.248 77.089,79.248 77.089,80.01 19.431,80.137 20.32,80.137 21.082,80.137 21.844,80.137 22.606,80.137 23.368,80.137 24.13,80.137 24.892,80.137 25.654,80.137 26.416,80.137 27.178,80.137 27.94,80.137 33.528,80.264 61.468,80.264 62.992,80.264 64.516,80.264 66.04,80.264 67.564,80.264 69.088,80.264 70.612,80.264 117.348,80.264 118.872,80.264 88.773,80.391 89.535,80.391 57.404,80.772 58.928,80.772 19.431,80.899 22.606,80.899 23.368,80.899 24.13,80.899 27.178,80.899 27.94,80.899 88.773,81.153 89.535,81.153 93.472,81.28 108.712,81.28 110.236,81.28 111.76,81.28 19.431,81.661 22.606,81.661 23.368,81.661 24.13,81.661 27.94,81.661 61.468,81.788 62.992,81.788 64.516,81.788 66.04,81.788 67.564,81.788 69.088,81.788 70.612,81.788 94.234,81.788 94.996,81.788 95.758,81.788 99.822,81.788 100.584,81.788 117.348,81.788 118.872,81.788 88.773,81.915 89.535,81.915 90.678,81.915 93.472,82.042 103.505,82.042 81.534,82.169 57.404,82.296 58.928,82.296 87.63,82.296 108.712,82.296 110.236,82.296 22.606,82.423 23.368,82.423 24.13,82.423 27.94,82.423 90.678,82.677 113.03,82.677 33.528,82.804 93.472,82.804 103.505,82.804 81.915,82.931 22.606,83.185 23.368,83.185 24.13,83.185 24.892,83.185 27.051,83.185 27.94,83.185 61.468,83.312 62.992,83.312 64.516,83.312 66.04,83.312 67.564,83.312 69.088,83.312 117.348,83.312 118.872,83.312 90.678,83.439 99.568,83.439 21.844,83.566 93.472,83.566 103.505,83.566 57.404,83.82 58.928,83.82 22.606,83.947 23.368,83.947 24.13,83.947 24.892,83.947 25.654,83.947 26.416,83.947 27.178,83.947 27.94,83.947 90.678,84.201 99.568,84.201 93.472,84.328 103.505,84.328 61.468,84.836 62.992,84.836 64.516,84.836 66.04,84.836 67.564,84.836 117.348,84.836 118.872,84.836 99.568,84.963 93.472,85.09 104.14,85.09 104.902,85.09 105.664,85.09 23.876,85.344 24.892,85.344 25.908,85.344 26.924,85.344 27.94,85.344 57.404,85.344 58.928,85.344 99.568,85.725 93.472,85.852 24.892,86.36 25.908,86.36 26.924,86.36 27.94,86.36 61.468,86.36 62.992,86.36 64.516,86.36 66.04,86.36 67.564,86.36 106.172,86.36 107.188,86.36 117.348,86.36 118.872,86.36 99.568,86.487 93.472,86.614 57.404,86.868 58.928,86.868 99.568,87.249 110.998,87.249 111.76,87.249 112.522,87.249 25.908,87.376 26.924,87.376 27.94,87.376 93.472,87.376 106.172,87.376 107.188,87.376 58.42,87.884 61.468,87.884 62.992,87.884 64.516,87.884 114.3,87.884 115.824,87.884 117.348,87.884 118.872,87.884 26.924,88.392 27.94,88.392 66.675,88.392 44.831,88.9 66.675,89.154 55.372,89.408 58.42,89.408 59.944,89.408 62.992,89.408 64.516,89.408 112.776,89.408 114.3,89.408 115.824,89.408 117.348,89.408 118.872,89.408 44.831,89.662 66.675,89.916 1.016,90.424 44.831,90.424 49.784,90.424 45.593,90.551 46.355,90.551 95.504,90.678 96.266,90.678 97.028,90.678 103.886,90.678 104.648,90.678 105.41,90.678 50.927,90.805 53.721,90.805 55.372,90.932 56.896,90.932 58.42,90.932 59.944,90.932 61.468,90.932 64.516,90.932 66.04,90.932 67.564,90.932 80.645,90.932 81.407,90.932 82.169,90.932 82.931,90.932 83.693,90.932 84.455,90.932 85.217,90.932 90.424,90.932 91.186,90.932 91.948,90.932 108.204,90.932 109.728,90.932 111.252,90.932 112.776,90.932 114.3,90.932 115.824,90.932 117.348,90.932 118.872,90.932 75.946,91.186 92.71,91.186 94.742,91.313 97.536,91.313 89.789,91.44 50.927,91.567 53.721,91.567 85.852,91.694 86.614,91.694 87.376,91.694 98.171,91.694 98.933,91.694 75.438,91.821 82.55,91.821 1.016,91.948 2.54,91.948 43.688,91.948 45.212,91.948 46.736,91.948 49.784,91.948 92.71,91.948 94.742,92.075 89.789,92.202 51.562,92.329 52.324,92.329 53.086,92.329 42.672,92.456 55.372,92.456 56.896,92.456 58.42,92.456 59.944,92.456 61.468,92.456 62.992,92.456 66.04,92.456 67.564,92.456 108.204,92.456 109.728,92.456 111.252,92.456 112.776,92.456 114.3,92.456 115.824,92.456 117.348,92.456 118.872,92.456 82.55,92.583 92.71,92.71 14.732,92.837 15.494,92.837 17.145,92.837 17.907,92.837 94.742,92.837 72.39,92.964 82.55,93.345 1.016,93.472 41.656,93.472 92.71,93.472 14.732,93.599 17.907,93.599 94.742,93.599 72.39,93.726 108.204,93.98 109.728,93.98 111.252,93.98 82.55,94.107 92.71,94.234 14.732,94.361 17.907,94.361 94.742,94.361 40.64,94.488 72.39,94.488 80.01,94.869 80.772,94.869 81.534,94.869 90.424,94.869 91.186,94.869 91.948,94.869 84.201,94.996 84.963,94.996 85.725,94.996 97.409,94.996 14.732,95.123 17.907,95.123 104.013,95.123 104.775,95.123 105.537,95.123 108.204,95.504 109.728,95.504 111.252,95.504 15.24,95.758 17.526,95.758 85.725,95.758 97.409,95.758 16.002,95.885 16.764,95.885 18.796,96.012 75.438,96.012 8.636,96.52 21.336,96.52 22.86,96.52 85.725,96.52 97.409,96.52 75.438,96.774 10.16,97.028 11.176,97.028 12.192,97.028 13.208,97.028 14.224,97.028 15.24,97.028 16.256,97.028 17.272,97.028 23.876,97.028 24.892,97.028 25.908,97.028 108.204,97.028 109.728,97.028 111.252,97.028 21.336,97.536 7.112,98.044 10.16,98.044 11.176,98.044 12.192,98.044 13.208,98.044 14.224,98.044 15.24,98.044 16.256,98.044 17.272,98.044 24.892,98.044 25.908,98.044 26.924,98.044 27.94,98.044 28.956,98.044 29.972,98.044 30.988,98.044 34.544,98.044 35.56,98.044 36.576,98.044 37.592,98.044 38.608,98.044 39.624,98.044 40.64,98.044 41.656,98.044 42.672,98.044 43.688,98.044 44.704,98.044 45.72,98.044 46.736,98.044 47.752,98.044 48.768,98.044 49.784,98.044 50.8,98.044 51.816,98.044 52.832,98.044 53.848,98.044 54.864,98.044 55.88,98.044 56.896,98.044 57.912,98.044 58.928,98.044 59.944,98.044 60.96,98.044 61.976,98.044 62.992,98.044 64.008,98.044 65.024,98.044 66.04,98.044 67.056,98.044 68.072,98.044 6.604,99.06 10.16,99.06 11.176,99.06 12.192,99.06 13.208,99.06 14.224,99.06 15.24,99.06 16.256,99.06 17.272,99.06 18.288,99.06 19.812,99.06 20.828,99.06 23.876,99.06 24.892,99.06 25.908,99.06 26.924,99.06 27.94,99.06 28.956,99.06 29.972,99.06 30.988,99.06 32.004,99.06 34.544,99.06 35.56,99.06 36.576,99.06 37.592,99.06 38.608,99.06 39.624,99.06 40.64,99.06 41.656,99.06 42.672,99.06 43.688,99.06 44.704,99.06 45.72,99.06 46.736,99.06 47.752,99.06 48.768,99.06 49.784,99.06 50.8,99.06 51.816,99.06 52.832,99.06 53.848,99.06 54.864,99.06 55.88,99.06 56.896,99.06 57.912,99.06 58.928,99.06 59.944,99.06 60.96,99.06 61.976,99.06 62.992,99.06 64.008,99.06 65.024,99.06 66.04,99.06 67.056,99.06 68.072,99.06 69.088,99.06 70.104,99.06 71.12,99.06 72.136,99.06 73.152,99.06 80.264,99.06 81.28,99.06 82.296,99.06 83.312,99.06 87.884,99.06 91.948,99.06 92.964,99.06 93.98,99.06 94.996,99.06 104.648,99.06 105.664,99.06 106.68,99.06 107.696,99.06 108.712,99.06 109.728,99.06 110.744,99.06 111.76,99.06 112.776,99.06 113.792,99.06
NetC1_2: C1.2 U1.15 | length 3.2
  Top Layer w0.25: U1.15@19.195,59.626 19.952,59.626 21.096,58.482 C1.2@21.096,57.607
NetC2_1: C2.1 R1.1 U1.8 U1.18 | length 13.1
  Top Layer w0.2: C2.1@13.755,60.833 C2.1@13.654,60.731 13.548,60.626 v1(14.652,60.626) U1.8@15.88,60.626 ; U1.18@19.195,61.126 20.23,61.126 v1(20.498,60.858) 20.555,60.916 20.744,60.916 21.652,61.824 R1.1@21.652,61.874
  Mid-Layer 2 w0.2: v1(14.652,60.626) 16.451,58.826 18.466,58.826 v1(20.498,60.858)
NetC4_2: C4.2 R3.2 U1.9 | length 20.3
  Top Layer w0.2: C4.2@13.654,59.08 13.857,59.284 14.3,59.284 15.142,60.126 U1.9@15.88,60.126
  Top Layer w0.25: R3.2@23.052,60.35 v1(24.079,60.35)
  Mid-Layer 1 w0.25: v1(14.677,59.635) 16.078,61.036 16.078,63.651 17.306,64.879 22.396,64.879 24.079,63.195 v1(24.079,60.35)
NetC6_1: C6.1 R4.2 | length 1.5
  Top Layer w0.5: C6.1@10.795,63.715 10.813,63.697 12.236,63.697 R4.2@12.254,63.679
NetC7_1: C7.1 R4.1 U1.5 | length 3.7
  Top Layer w0.2: R4.1@13.654,63.679 C7.1@13.654,62.205 13.693,62.166 15.84,62.166 U1.5@15.88,62.126
NetF1_1: F1.1 P3.10
NetL1_2: L1.2 R2.1 U1.20 | length 43.1
  Top Layer w0.25: U1.20@19.195,62.126 19.784,62.126 20.955,63.297 21.361,63.297 v1(21.59,63.068)
  Mid-Layer 1 w0.25: v1(14.605,33.147) 14.605,32.487 15.037,32.055 20.625,32.055 22.86,34.29 22.86,62.814 22.301,63.373 21.895,63.373 v1(21.59,63.068)
  other v1: 9.271,33.147 10.033,33.147 10.795,33.147 11.557,33.147 12.319,33.147 13.081,33.147 13.843,33.147 15.367,33.147 16.129,33.147 16.891,33.147 17.653,33.147 18.415,33.147 19.177,33.147 19.939,33.147 9.271,33.909 10.033,33.909 10.795,33.909 11.557,33.909 12.319,33.909 13.081,33.909 13.843,33.909 14.605,33.909 15.367,33.909 16.129,33.909 16.891,33.909 17.653,33.909 18.415,33.909 19.177,33.909 19.939,33.909 9.271,34.671 10.033,34.671 10.795,34.671 11.557,34.671 12.319,34.671 13.081,34.671 13.843,34.671 14.605,34.671 15.367,34.671 16.129,34.671 16.891,34.671 17.653,34.671 18.415,34.671 19.177,34.671 19.939,34.671 9.271,35.433 10.033,35.433 10.795,35.433 11.557,35.433 12.319,35.433 13.081,35.433 13.843,35.433 14.605,35.433 15.367,35.433 16.129,35.433 16.891,35.433 17.653,35.433 18.415,35.433 19.177,35.433 19.939,35.433 9.271,36.195 10.033,36.195 10.795,36.195 11.557,36.195 12.319,36.195 13.081,36.195 13.843,36.195 14.605,36.195 15.367,36.195 16.129,36.195 16.891,36.195 17.653,36.195 18.415,36.195 19.177,36.195 19.939,36.195 9.271,36.957 10.033,36.957 10.795,36.957 11.557,36.957 12.319,36.957 13.081,36.957 13.843,36.957 14.605,36.957 15.367,36.957 16.129,36.957 16.891,36.957 17.653,36.957 18.415,36.957 19.177,36.957 19.939,36.957 9.271,37.719 10.033,37.719 10.795,37.719 11.557,37.719 12.319,37.719 13.081,37.719 13.843,37.719 14.605,37.719 15.367,37.719 16.129,37.719 16.891,37.719 17.653,37.719 18.415,37.719 19.177,37.719 19.939,37.719 9.271,38.481 10.033,38.481 10.795,38.481 11.557,38.481 12.319,38.481 13.081,38.481 13.843,38.481 14.605,38.481 15.367,38.481 16.129,38.481 16.891,38.481 17.653,38.481 18.415,38.481 19.177,38.481 19.939,38.481 9.271,39.243 10.033,39.243 10.795,39.243 11.557,39.243 12.319,39.243 13.081,39.243 13.843,39.243 14.605,39.243 15.367,39.243 16.129,39.243 16.891,39.243 17.653,39.243 18.415,39.243 19.177,39.243 19.939,39.243
NetMOD1_6: MOD1.6 R17.1 | length 8.1
  Top Layer w0.25: MOD1.6@76.073,43.409 77.939,41.543 R17.1@77.939,36.043
NetP13_2: P13.2 Q3.2
NetQ1_4: Q1.4 U1.13 | length 9
  Top Layer w0.25: Q1.4@13.589,52.006 13.732,52.149 14.303,52.149 v1(14.351,52.197)
  Top Layer w0.3: v1(17.628,55.956) 18.288,56.617 U1.13@18.288,58.718
  Mid-Layer 1 w0.3: v1(14.351,52.197) 17.628,55.474 v1(17.628,55.956)
NetQ2_4: Q2.4 U1.11 | length 11.2
  Top Layer w0.25: v1(15.24,58.674) 15.24,58.678 15.688,59.126 U1.11@15.88,59.126 ; v1(21.082,53.086) 21.082,52.014 Q2.4@21.137,51.959
  Mid-Layer 1 w0.25: v1(15.24,58.674) 15.24,58.014 16.078,57.175 18.136,57.175 21.082,54.229 v1(21.082,53.086)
